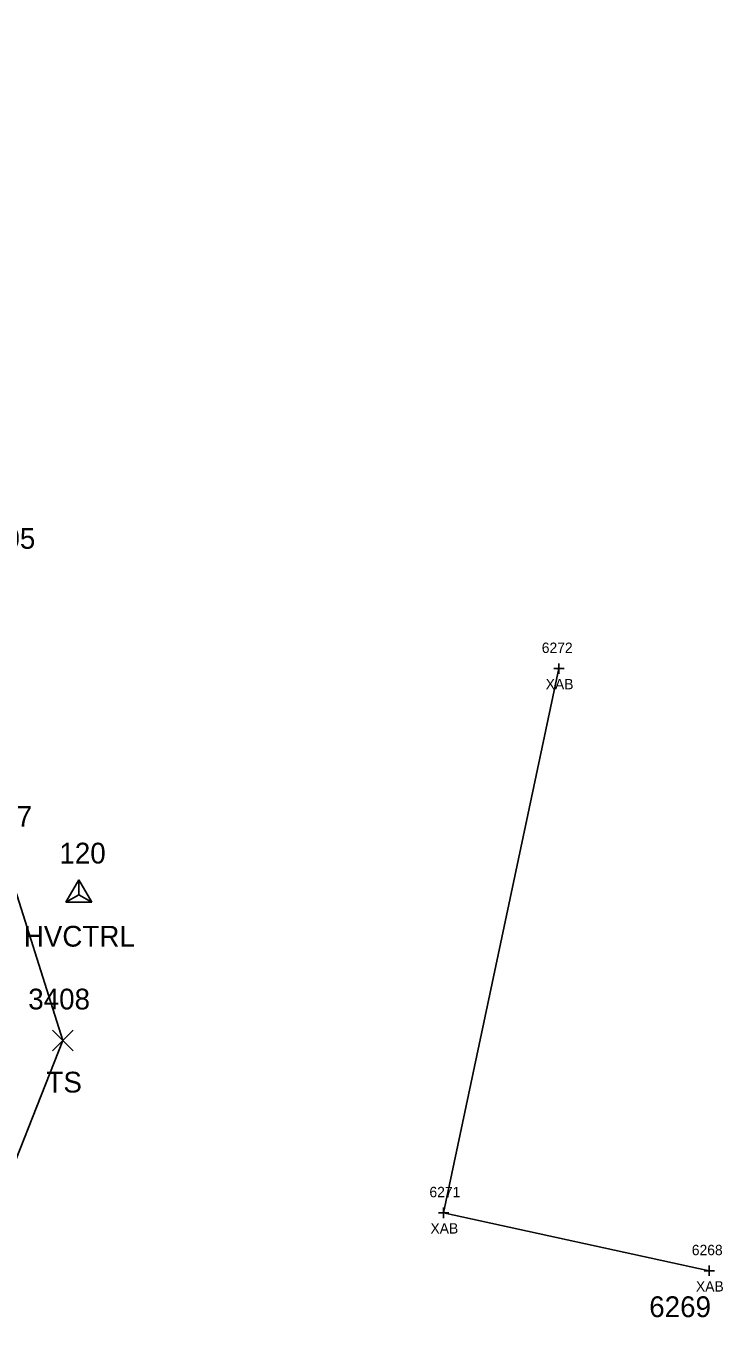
# Model space of a CAD drawing. Extents: x 1462668 to 1465147, y 550359 to 557351.
# Drawn here: x 1465006.3 to 1465073.4, y 551584.4 to 551709.5 of the extents above; entities that cross this region are included whole.
import ezdxf

# ---------------------------------------------------------------- set-up
doc = ezdxf.new("R2010")
doc.units = 0
for name, color, linetype in [('B_A', 7, 'Continuous'), ('B_I', 7, 'Continuous'), ('B_TIC', 7, 'Continuous'), ('BSUBM', 7, 'Continuous'), ('C_A', 7, 'Continuous'), ('C_I', 7, 'Continuous'), ('CPSM', 7, 'Continuous'), ('L_A', 7, 'Continuous'), ('L_I', 7, 'Continuous'), ('L_TIC', 7, 'Continuous'), ('LELB', 7, 'Continuous'), ('Level 6', 7, 'Continuous'), ('U_I', 7, 'Continuous')]:
    doc.layers.add(name, color=color, linetype=linetype)

msp = doc.modelspace()

# ---------------------------------------------------------------- linework, layer by layer
at = {"layer": 'B_TIC'}
for p, q in [((1465057.6, 551647.65), (1465057.68, 551647.65)), ((1465046.5, 551595.25), (1465046.57, 551595.25)), ((1465072.07, 551589.67), (1465072.15, 551589.67))]:
    msp.add_line(p, q, dxfattribs=at)
for points in [[(1465057.1, 551647.65), (1465058.1, 551647.65)], [(1465057.6, 551647.15), (1465057.6, 551648.15)], [(1465045.99, 551595.25), (1465046.99, 551595.25)], [(1465046.49, 551594.75), (1465046.49, 551595.75)], [(1465072.07, 551589.17), (1465072.07, 551590.17)], [(1465071.57, 551589.67), (1465072.57, 551589.67)]]:
    msp.add_lwpolyline(points, dxfattribs=at)
at = {"layer": 'BSUBM'}
msp.add_lwpolyline([(1465072.07, 551589.67), (1465046.49, 551595.25), (1465057.6, 551647.65)], dxfattribs=at)
at = {"layer": 'CPSM'}
for p, q in [((1465010.11, 551625.16), (1465011.36, 551627.32)), ((1465012.61, 551625.16), (1465011.36, 551627.32)), ((1465011.36, 551625.88), (1465011.36, 551627.32)), ((1465010.11, 551625.16), (1465011.36, 551625.88)), ((1465010.11, 551625.16), (1465012.61, 551625.16)), ((1465011.36, 551625.88), (1465011.36, 551625.88)), ((1465011.36, 551625.88), (1465012.61, 551625.16))]:
    msp.add_line(p, q, dxfattribs=at)
at = {"layer": 'L_TIC'}
for points in [[(1465008.82, 551610.83), (1465010.82, 551612.83)], [(1465010.82, 551610.83), (1465008.82, 551612.83)]]:
    msp.add_lwpolyline(points, dxfattribs=at)
at = {"layer": 'LELB'}
msp.add_lwpolyline([(1465004.55, 551656.18), (1464996.92, 551647.78), (1465004.25, 551629.42), (1465009.82, 551611.83)], dxfattribs=at)
at = {"layer": 'Level 6'}
msp.add_lwpolyline([(1465006.63, 551555.62), (1465002.76, 551593.99), (1465009.82, 551611.83), (1465004.25, 551629.42), (1465004.55, 551656.18), (1464996.97, 551667.75), (1464995.18, 551683.47), (1464987.6, 551730.67), (1464983.27, 551780.9), (1464985.17, 551830.5), (1464983.42, 551852.54)], dxfattribs=at)

# ---------------------------------------------------------------- texts
at = {"layer": 'B_A'}
for p in [(1465056.32, 551645.65), (1465045.22, 551593.25), (1465070.79, 551587.67)]:
    msp.add_text('XAB', height=1, dxfattribs=at).set_placement(p)
at = {"layer": 'B_I'}
for s, p in [('6272', (1465055.94, 551649.15)), ('6271', (1465045.12, 551596.75)), ('6268', (1465070.39, 551591.17))]:
    msp.add_text(s, height=1, dxfattribs=at).set_placement(p)
at = {"layer": 'C_A'}
msp.add_text('HVCTRL', height=2, dxfattribs=at).set_placement((1465006.05, 551620.88))
at = {"layer": 'C_I'}
msp.add_text('120', height=2, dxfattribs=at).set_placement((1465009.48, 551628.88))
at = {"layer": 'L_A'}
msp.add_text('TS', height=2, dxfattribs=at).set_placement((1465008.23, 551606.83))
at = {"layer": 'L_I'}
for s, p in [('3405', (1465001.21, 551659.18)), ('3407', (1465000.91, 551632.42)), ('3408', (1465006.48, 551614.83))]:
    msp.add_text(s, height=2, dxfattribs=at).set_placement(p)
at = {"layer": 'U_I'}
msp.add_text('6269', height=2, dxfattribs=at).set_placement((1465066.29, 551585.21))

doc.saveas('drawing.dxf')
